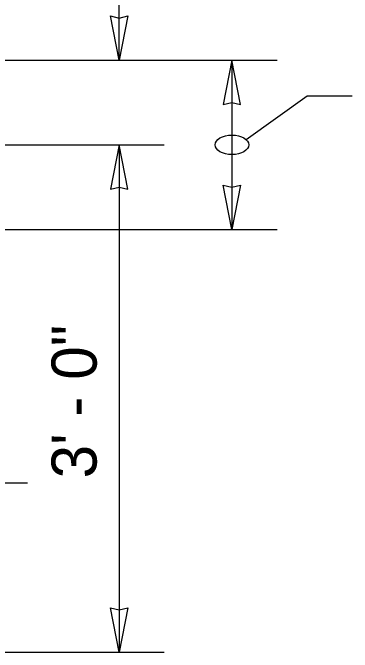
# Model space of a CAD drawing. Extents: x 99888 to 103177, y 100000 to 102076.
# Drawn here: x 102162.4 to 102282.8, y 101075.3 to 101302.1 of the extents above; entities that cross this region are included whole.
import ezdxf

# ---------------------------------------------------------------- set-up
doc = ezdxf.new("R2010")
doc.units = 0
doc.layers.add('Level 15', color=7, linetype='Continuous')
doc.layers.add('Level 20', color=7, linetype='Continuous')

msp = doc.modelspace()

# ---------------------------------------------------------------- linework, layer by layer
at = {"layer": 'Level 15'}
for p, q in [((102200.13, 101285.28), (102200.13, 101325.06)), ((102200.13, 101285.28), (102200.13, 101325.06)), ((102045.16, 101285.28), (102256.13, 101285.28)), ((102045.16, 101285.28), (102256.13, 101285.28)), ((102240.13, 101285.28), (102240.13, 101225.28)), ((102240.13, 101285.28), (102240.13, 101225.28)), ((102245.14, 101257.16), (102266.8, 101272.69)), ((102266.8, 101272.69), (102282.8, 101272.69)), ((102096.13, 101255.28), (102216.13, 101255.28)), ((102096.13, 101255.28), (102216.13, 101255.28)), ((102200.13, 101255.28), (102200.13, 101075.28)), ((102200.13, 101255.28), (102200.13, 101075.28)), ((102043.09, 101225.28), (102192.13, 101225.28)), ((102043.09, 101225.28), (102208.13, 101225.28)), ((102208.13, 101225.28), (102256.13, 101225.28)), ((102208.13, 101225.28), (102256.13, 101225.28)), ((102167.66, 101135.28), (102080.13, 101135.28)), ((102167.66, 101135.28), (102080.13, 101135.28)), ((102096.13, 101075.28), (102216.13, 101075.28)), ((102096.13, 101075.28), (102216.13, 101075.28))]:
    msp.add_line(p, q, dxfattribs=at)
for points in [[(102200.13, 101285.28), (102197.05, 101301), (102200.13, 101300.27), (102203.22, 101301)], [(102200.13, 101285.28), (102197.05, 101301), (102200.13, 101300.27), (102203.22, 101301)], [(102240.13, 101285.28), (102237.05, 101269.55), (102240.13, 101270.28), (102243.22, 101269.55)], [(102240.13, 101285.28), (102237.05, 101269.55), (102240.13, 101270.28), (102243.22, 101269.55)], [(102200.13, 101255.28), (102197.05, 101239.55), (102200.13, 101240.28), (102203.22, 101239.55)], [(102200.13, 101255.28), (102197.05, 101239.55), (102200.13, 101240.28), (102203.22, 101239.55)], [(102240.13, 101225.28), (102237.05, 101241), (102240.13, 101240.27), (102243.22, 101241)], [(102240.13, 101225.28), (102237.05, 101241), (102240.13, 101240.27), (102243.22, 101241)], [(102200.13, 101075.28), (102197.05, 101091), (102200.13, 101090.27), (102203.22, 101091)], [(102200.13, 101075.28), (102197.05, 101091), (102200.13, 101090.27), (102203.22, 101091)]]:
    msp.add_lwpolyline(points, close=True, dxfattribs=at)
msp.add_ellipse((102240.13, 101255.28), major_axis=(-6, 0), ratio=0.57735, dxfattribs=at)
msp.add_ellipse((102240.13, 101255.28), major_axis=(-6, 0), ratio=0.57735, dxfattribs=at)

# ---------------------------------------------------------------- texts
at = {"layer": 'Level 20'}
msp.add_text('3\' - 0"', height=16, rotation=90, dxfattribs=at).set_placement((102192.13, 101136.94))
msp.add_text('3\' - 0"', height=16, rotation=90, dxfattribs=at).set_placement((102192.13, 101136.94))

doc.saveas('drawing.dxf')
